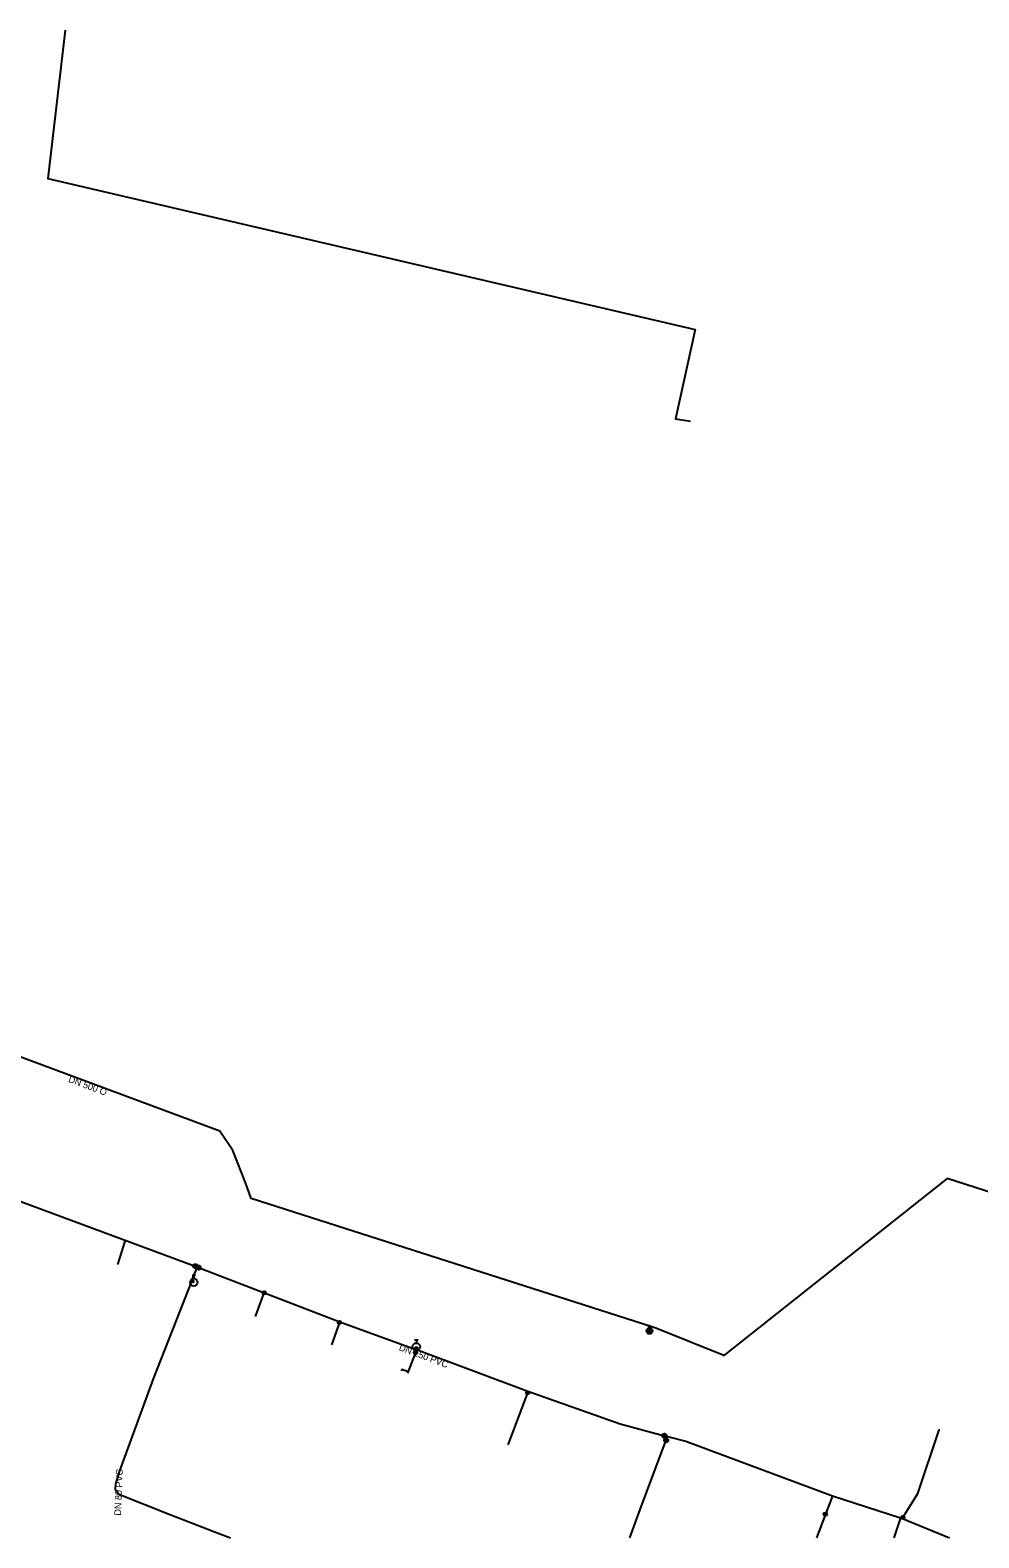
# Model space of a CAD drawing. Extents: x -464617 to -463917, y -1094288 to -1093929.
# Drawn here: x -464420.1 to -464194.4, y -1094287.7 to -1093929.4 of the extents above; entities that cross this region are included whole.
import ezdxf

# ---------------------------------------------------------------- set-up
doc = ezdxf.new("R2010")
doc.units = 0
for name, color, linetype in [('_hydrantova_odbocka_', 7, 'Continuous'), ('_pripojka_priblizne_', 7, 'Continuous'), ('_voda_smvak_prevzato_z_dokumentace_', 7, 'Continuous'), ('Default', 7, 'Continuous'), ('MoLevel 27', 7, 'Continuous'), ('MoLevel 28', 7, 'Continuous'), ('MoLevel 30', 7, 'Continuous'), ('MoLevel 42', 7, 'Continuous'), ('MoLevel 46', 7, 'Continuous'), ('MoLevel 53', 7, 'Continuous')]:
    doc.layers.add(name, color=color, linetype=linetype)

# ---------------------------------------------------------------- blocks, each defined once
blk = doc.blocks.new('_uzaver_')
at = {"layer": 'Default'}
for p, q in [((-0.000035, -0.000035), (0.000035, 0.000035)), ((0.000035, -0.000035), (-0.000035, 0.000035))]:
    blk.add_line(p, q, dxfattribs=at)
for radius in [0.00005, 0.0000025]:
    blk.add_circle((0, 0), radius, dxfattribs=at)
blk = doc.blocks.new('_uzaver_pripojka_')
at = {"layer": 'Default'}
for p, q in [((-0.000035, -0.000035), (0.000035, 0.000035)), ((0.000035, -0.000035), (-0.000035, 0.000035))]:
    blk.add_line(p, q, dxfattribs=at)
for radius in [0.00005, 0.0000025]:
    blk.add_circle((0, 0), radius, dxfattribs=at)
blk = doc.blocks.new('_hydrant_voda_')
at = {"layer": 'Default'}
for p, q in [((-0.000023, 0.000095), (0.000023, 0.000095)), ((0, 0.000095), (0, 0.00005))]:
    blk.add_line(p, q, dxfattribs=at)
blk.add_circle((0, 0), 0.00005, dxfattribs=at)
blk = doc.blocks.new('_sachta_voda_')
at = {"layer": 'Default'}
blk.add_line((0, 0.000035), (0, 0.00005), dxfattribs=at)
blk.add_lwpolyline([(-0.000015, 0.00005), (0, 0.000065), (0.000015, 0.00005), (0.000003, 0.00005)], close=True, dxfattribs=at)
blk.add_circle((0, 0), 0.000035, dxfattribs=at)
blk = doc.blocks.new('_poklop_voda_')
at = {"layer": 'Default'}
blk.add_lwpolyline([(-0.00002, 0.00002), (0.00002, 0.00002), (0.00002, -0.00002), (-0.00002, -0.00002), (-0.00002, 0.00002)], dxfattribs=at)

msp = doc.modelspace()

# ---------------------------------------------------------------- linework, layer by layer
at = {"layer": '_hydrantova_odbocka_'}
for points in [[(-464381.67, -1094226.59), (-464381.4, -1094226.8), (-464381.15, -1094226.99)], [(-464328.36, -1094242.91), (-464328.24, -1094242.61), (-464328.23, -1094242.28)]]:
    msp.add_lwpolyline(points, dxfattribs=at)
at = {"layer": '_pripojka_priblizne_'}
for p, q in [((-464399.24, -1094222.71), (-464397.37, -1094216.99)), ((-464213.09, -1094282.95), (-464214.69, -1094287.71))]:
    msp.add_line(p, q, dxfattribs=at)
for points in [[(-464411.77, -1093929.4), (-464415.87, -1093964.68), (-464261.94, -1094000.55), (-464266.58, -1094021.78), (-464263, -1094022.34)], [(-464366.49, -1094235.12), (-464364.42, -1094229.46), (-464364.85, -1094229.29)], [(-464346.47, -1094236.34), (-464346.53, -1094236.5), (-464348.44, -1094241.86)], [(-464328.23, -1094242.96), (-464328.43, -1094243.66), (-464330.36, -1094248.61)], [(-464330.21, -1094248.24), (-464331.7, -1094247.69), (-464331.85, -1094247.98)], [(-464301.7, -1094252.87), (-464301.78, -1094253.22), (-464306.44, -1094265.64)], [(-464212.59, -1094283.09), (-464212.53, -1094282.84), (-464209, -1094277.19), (-464203.88, -1094262.05), (-464203.75, -1094262.08)], [(-464229.28, -1094277.72), (-464230.96, -1094282.08), (-464233.03, -1094287.71)]]:
    msp.add_lwpolyline(points, dxfattribs=at)
at = {"layer": '_voda_smvak_prevzato_z_dokumentace_'}
for p, q in [((-464380.8, -1094223.12), (-464380.38, -1094223.31)), ((-464380.38, -1094223.31), (-464380.01, -1094223.48)), ((-464269.25, -1094263.45), (-464268.51, -1094263.65)), ((-464268.82, -1094264.53), (-464268.51, -1094263.65))]:
    msp.add_line(p, q, dxfattribs=at)
for points in [[(-463938.35, -1094193.12), (-464075.49, -1094227.95), (-464134.41, -1094223.46), (-464163.79, -1094214.62), (-464202, -1094202.35), (-464255.09, -1094244.35), (-464271.29, -1094237.84), (-464272.2, -1094237.58), (-464367.49, -1094207.05), (-464368.8, -1094203.51), (-464371.89, -1094195.64), (-464375, -1094191.05), (-464437.3, -1094167.91), (-464498.99, -1094146.23), (-464538.72, -1094132.85), (-464555.61, -1094126.9), (-464559.83, -1094125.15), (-464564.5, -1094123.44), (-464565.5, -1094123.21)], [(-464474.73, -1094188.39), (-464456.17, -1094195.24), (-464380.8, -1094223.12)], [(-464380.38, -1094223.31), (-464381.64, -1094226.34), (-464381.67, -1094226.59)], [(-464380.01, -1094223.48), (-464346.47, -1094236.34), (-464328.36, -1094242.91)], [(-464381.67, -1094226.59), (-464390.83, -1094249.95), (-464398.86, -1094271.78), (-464399.78, -1094274.9), (-464399.83, -1094276.18), (-464398.98, -1094277.32), (-464387.06, -1094282.08), (-464376.41, -1094286.24), (-464372.43, -1094287.71)], [(-464328.36, -1094242.91), (-464328.23, -1094242.96), (-464301.7, -1094252.87), (-464279.79, -1094260.61), (-464269.25, -1094263.45)], [(-464277.44, -1094287.71), (-464274.69, -1094280.1), (-464268.82, -1094264.53)], [(-464268.51, -1094263.65), (-464264.17, -1094264.76), (-464229.28, -1094277.72), (-464213.09, -1094282.95), (-464212.59, -1094283.09), (-464201.44, -1094287.71)]]:
    msp.add_lwpolyline(points, dxfattribs=at)

# ---------------------------------------------------------------- block references
at = {"layer": 'MoLevel 27'}
for p, xscale, yscale, rotation in [((-464380.8, -1094223.13), 10000, 10000, 159.570840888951), ((-464380.01, -1094223.48), 10000, 9999.999999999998, -20.96788539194), ((-464381.4, -1094226.8), 5000, 5000.000000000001, -32.005383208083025), ((-464328.24, -1094242.61), 5000, 4999.999999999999, 87.27368900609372), ((-464269.25, -1094263.45), 10000, 10000, 164.920310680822), ((-464268.82, -1094264.53), 10000.000000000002, 10000.000000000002, -110.65884109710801)]:
    msp.add_blockref('_uzaver_', p, dxfattribs=dict(at, xscale=xscale, yscale=yscale, rotation=rotation))
at = {"layer": 'MoLevel 28', "xscale": 17636.68430335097, "yscale": 17636.68430335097}
for p in [(-464381.15, -1094226.99), (-464328.23, -1094242.29)]:
    msp.add_blockref('_hydrant_voda_', p, dxfattribs=at)
at = {"layer": 'MoLevel 30', "xscale": 20000, "yscale": 20000}
msp.add_blockref('_sachta_voda_', (-464272.8, -1094238.55), dxfattribs=at)
at = {"layer": 'MoLevel 42', "xscale": 10000, "yscale": 10000}
msp.add_blockref('_poklop_voda_', (-464272.8, -1094238.55), dxfattribs=at)
at = {"layer": 'MoLevel 53', "xscale": 7999.999999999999, "yscale": 7999.999999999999}
for p in [(-464364.43, -1094229.48), (-464346.53, -1094236.5), (-464328.43, -1094243.66), (-464301.78, -1094253.22), (-464230.96, -1094282.08), (-464212.53, -1094282.84)]:
    msp.add_blockref('_uzaver_pripojka_', p, dxfattribs=at)

# ---------------------------------------------------------------- texts
at = {"layer": 'MoLevel 46'}
for s, rotation, p in [('DN 500 O', 339.6244, (-464411.14, -1094179.34)), ('DN 150 PVC', 339.52, (-464332.51, -1094243.08)), ('DN 80 PVC', 87.6308, (-464398.49, -1094282.46))]:
    msp.add_text(s, height=1.605, rotation=rotation, dxfattribs=at).set_placement(p)

doc.saveas('drawing.dxf')
